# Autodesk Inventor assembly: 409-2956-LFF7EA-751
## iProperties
Created: 2010-06
Part Number: 409-2956-LFF7EA-751
Document SubType Name: Weldment
Designer: S. Boerckel
Mass: 5271.29 g
Surface Area: 1757.7 cm^2
Volume: 670.829 cm^3
Density: 7.85787 g/cm^3
Description: RECIRCULATION SPOOL
Weld Material: Welded Steel Mild
User Status: WELD
Material: WEDLMENT
SMR: =<MATERIAL>
Author: S. Boerckel
Revision Number: B
Subject: DEMIN WATER FORWARDING PUMP SKID-7EA
